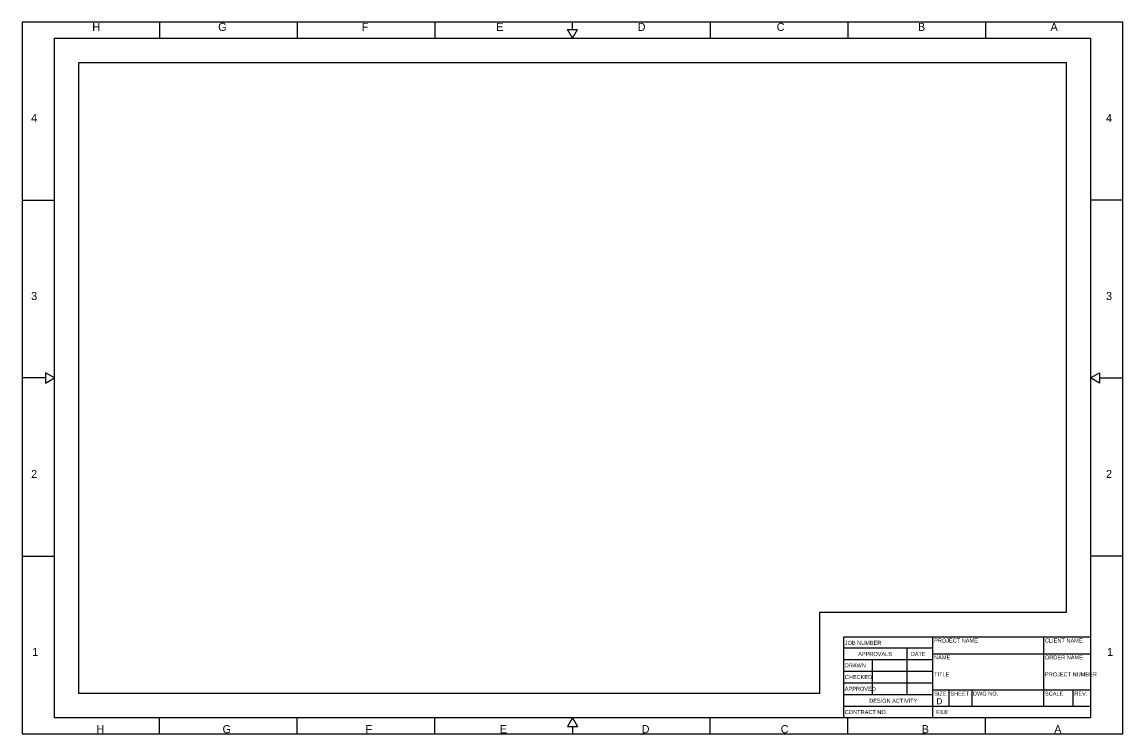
# Model space of a CAD drawing. Extents: x 0 to 2.83, y 0 to 1.83.
import ezdxf

# ---------------------------------------------------------------- set-up
doc = ezdxf.new("R2010")
doc.units = 0
for name, color, linetype in [('Border', 7, 'Continuous'), ('BorderPlot', 7, 'Continuous'), ('ClipShape', 7, 'Continuous'), ('TitleBlock', 7, 'Continuous'), ('TitleBlockText', 7, 'Continuous')]:
    doc.layers.add(name, color=color, linetype=linetype)

msp = doc.modelspace()

# ---------------------------------------------------------------- linework, layer by layer
at = {"layer": 'Border'}
for p, q in [((0.3542, 1.8333), (0.3542, 1.7917)), ((0.7083, 1.8333), (0.7083, 1.7917)), ((1.0625, 1.8333), (1.0625, 1.7917)), ((1.4167, 1.7917), (1.4036, 1.8143)), ((1.4036, 1.8143), (1.4297, 1.8143)), ((1.4167, 1.8143), (1.4167, 1.8333)), ((1.4167, 1.7917), (1.4297, 1.8143)), ((1.7708, 1.8333), (1.7708, 1.7917)), ((2.125, 1.8333), (2.125, 1.7917)), ((2.4792, 1.8333), (2.4792, 1.7917)), ((0, 1.375), (0.0833, 1.375)), ((2.8333, 1.375), (2.75, 1.375)), ((0.0607, 0.9167), (0, 0.9167)), ((0.0833, 0.9167), (0.0607, 0.9297)), ((0.0607, 0.9297), (0.0607, 0.9036)), ((0.0607, 0.9036), (0.0833, 0.9167)), ((2.75, 0.9167), (2.7726, 0.9297)), ((2.7726, 0.9036), (2.75, 0.9167)), ((2.7726, 0.9297), (2.7726, 0.9036)), ((2.7726, 0.9167), (2.8333, 0.9167)), ((0, 0.4583), (0.0833, 0.4583)), ((2.8333, 0.4583), (2.75, 0.4583)), ((0.3542, 0), (0.3542, 0.0417)), ((0.7083, 0), (0.7083, 0.0417)), ((1.0625, 0), (1.0625, 0.0417)), ((1.4167, 0.0417), (1.4036, 0.0191)), ((1.4167, 0.0417), (1.4297, 0.0191)), ((1.7708, 0), (1.7708, 0.0417)), ((2.125, 0), (2.125, 0.0417)), ((2.4792, 0), (2.4792, 0.0417)), ((1.4036, 0.0191), (1.4297, 0.0191)), ((1.4167, 0.0191), (1.4167, 0))]:
    msp.add_line(p, q, dxfattribs=at)
msp.add_lwpolyline([(2.75, 0.0417), (0.0833, 0.0417), (0.0833, 1.7917), (2.75, 1.7917)], close=True, dxfattribs=at)
at = {"layer": 'BorderPlot'}
msp.add_lwpolyline([(0, 0), (2.8333, 0), (2.8333, 1.8333), (0, 1.8333)], close=True, dxfattribs=at)
at = {"layer": 'ClipShape'}
for p, q in [((0.1458, 0.1042), (0.1458, 1.7292)), ((0.1458, 1.7292), (2.6875, 1.7292)), ((2.6875, 1.7292), (2.6875, 0.3125)), ((2.6875, 0.3125), (2.0525, 0.3125)), ((2.0525, 0.3125), (2.0525, 0.1042)), ((2.0525, 0.1042), (0.1458, 0.1042))]:
    msp.add_line(p, q, dxfattribs=at)
at = {"layer": 'TitleBlock'}
for p, q in [((2.115, 0.0417), (2.115, 0.25)), ((2.115, 0.25), (2.75, 0.25)), ((2.3442, 0.0417), (2.3442, 0.25)), ((2.6293, 0.0717), (2.6293, 0.25)), ((2.115, 0.2217), (2.3442, 0.2217)), ((2.2782, 0.1017), (2.2782, 0.2217)), ((2.3442, 0.2067), (2.75, 0.2067)), ((2.115, 0.1917), (2.3442, 0.1917)), ((2.1883, 0.1017), (2.1883, 0.1917)), ((2.115, 0.1617), (2.3442, 0.1617)), ((2.115, 0.1317), (2.3442, 0.1317)), ((2.115, 0.1017), (2.3442, 0.1017)), ((2.3442, 0.1133), (2.75, 0.1133)), ((2.3858, 0.0717), (2.3858, 0.1133)), ((2.4451, 0.0717), (2.4451, 0.1133)), ((2.7049, 0.0717), (2.7049, 0.1133)), ((2.115, 0.0717), (2.75, 0.0717)), ((2.75, 0.0417), (2.75, 0.0417))]:
    msp.add_line(p, q, dxfattribs=at)

# ---------------------------------------------------------------- texts
at = {"layer": 'Border'}
for s, p in [('H', (0.1808, 1.8104)), ('G', (0.5049, 1.8104)), ('F', (0.8743, 1.8104)), ('E', (1.2202, 1.8104)), ('D', (1.5843, 1.8104)), ('C', (1.9423, 1.8104)), ('B', (2.3057, 1.8104)), ('A', (2.6468, 1.8104)), ('4', (0.0235, 1.5758)), ('4', (2.7897, 1.5758)), ('3', (0.0235, 1.1174)), ('3', (2.7897, 1.1174)), ('2', (0.0235, 0.6591)), ('2', (2.7897, 0.6591)), ('1', (0.0261, 0.2008)), ('1', (2.7923, 0.2008)), ('H', (0.1912, 0.0021)), ('G', (0.5161, 0.0021)), ('F', (0.8839, 0.0021)), ('E', (1.2298, 0.0021)), ('D', (1.5946, 0.0021)), ('C', (1.9526, 0.0021)), ('B', (2.3153, 0.0021)), ('A', (2.6564, 0.0021))]:
    msp.add_text(s, height=0.0208, dxfattribs=at).set_placement(p)
at = {"layer": 'TitleBlock'}
msp.add_text('D', height=0.0156, dxfattribs=at).set_placement((2.3532, 0.0766))
at = {"layer": 'TitleBlockText'}
for s, height, p in [('JOB NUMBER', 0.01042, (2.1173, 0.2295)), ('PROJECT NAME', 0.010417, (2.3473, 0.2355)), ('CLIENT NAME', 0.010417, (2.6326, 0.2355)), ('APPROVALS', 0.01042, (2.1517, 0.2008)), ('DATE', 0.01042, (2.2872, 0.2008)), ('NAME', 0.01042, (2.3473, 0.1921)), ('ORDER NAME', 0.01042, (2.6326, 0.1921)), ('DRAWN', 0.01042, (2.1173, 0.1715)), ('CHECKED', 0.01042, (2.1173, 0.1413)), ('TITLE', 0.01042, (2.3473, 0.1483)), ('PROJECT NUMBER', 0.010417, (2.6326, 0.1483)), ('APPROVED', 0.01042, (2.1173, 0.1111)), ('DESIGN ACTIVITY', 0.010417, (2.1802, 0.0803)), ('SIZE', 0.01042, (2.3473, 0.0988)), ('SHEET', 0.01042, (2.389, 0.0988)), ('DWG NO.', 0.01042, (2.4474, 0.0988)), ('SCALE', 0.01042, (2.6326, 0.0988)), ('REV.', 0.01042, (2.7082, 0.0988)), ('CONTRACT NO.', 0.010417, (2.1173, 0.0512)), ('FILE', 0.01042, (2.3528, 0.0513))]:
    msp.add_text(s, height=height, dxfattribs=at).set_placement(p)

doc.saveas('drawing.dxf')
